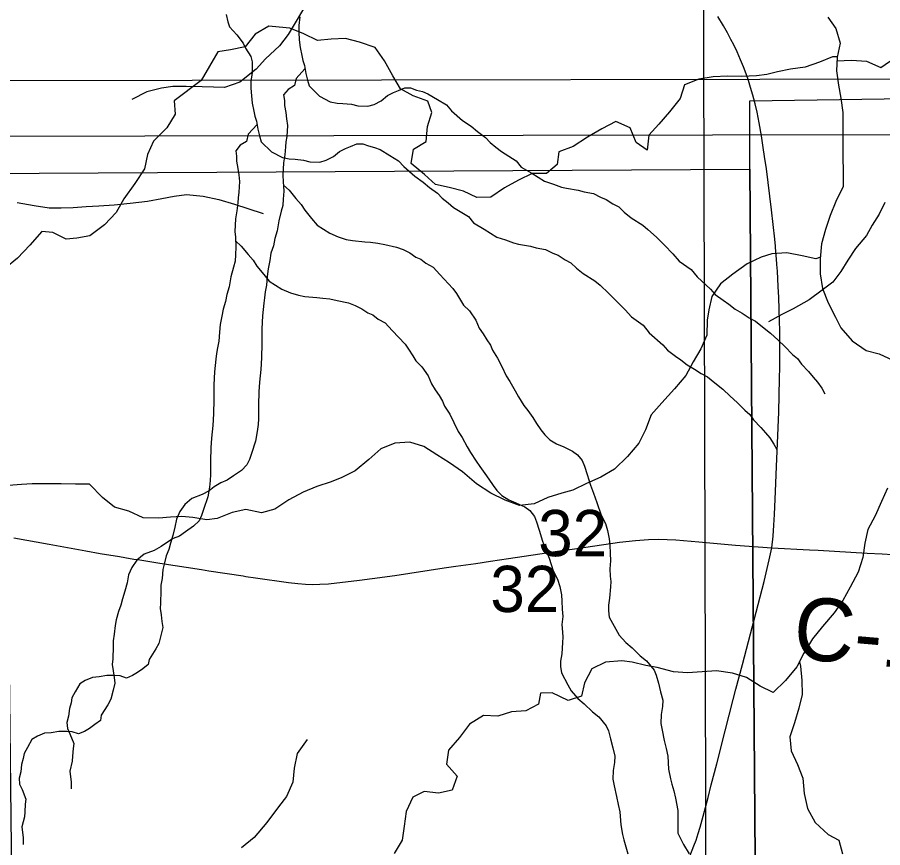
# Model space of a CAD drawing. Extents: x -21.1 to 50.3, y 0 to 22.1.
# Drawn here: x 3.837 to 4.62, y 19.324 to 20.075 of the extents above; entities that cross this region are included whole.
import ezdxf

# ---------------------------------------------------------------- set-up
doc = ezdxf.new("R2010")
doc.units = 0
for name, color, linetype in [('GM_X_County_Road', 7, 'Continuous'), ('GM_X_County_Road_Text', 7, 'Continuous'), ('GM_X_Minor_River', 7, 'Continuous'), ('GM_X_Section', 7, 'Continuous'), ('GM_X_Section_Text', 7, 'Continuous'), ('GM_X_State_Route', 7, 'Continuous'), ('GM_X_Township_Road', 7, 'Continuous')]:
    doc.layers.add(name, color=color, linetype=linetype)

msp = doc.modelspace()

# ---------------------------------------------------------------- linework, layer by layer
at = {"layer": 'GM_X_County_Road'}
msp.add_lwpolyline([(4.5196, 19.59528), (4.55358, 19.59321), (4.56138, 19.5929), (4.60576, 19.5903), (4.61927, 19.58967), (4.64742, 19.58801), (4.6643, 19.58714), (4.68714, 19.58536), (4.72573, 19.58133)], dxfattribs=at)
at = {"layer": 'GM_X_Minor_River'}
for points in [[(4.09721, 20.08514), (4.09, 20.07339), (4.08203, 20.05973), (4.07406, 20.04949), (4.06155, 20.03773), (4.0532, 20.02825), (4.03841, 20.01649), (4.02439, 20.01156), (4.01453, 20.01194), (4.00429, 20.01231), (3.98989, 20.01269), (3.97776, 20.01269), (3.96752, 20.01117), (3.95425, 20.00776), (3.9406, 20.00093)], [(4.02587, 20.07787), (4.02743, 20.07105), (4.02898, 20.0665), (4.03549, 20.05932), (4.04124, 20.05175), (4.04355, 20.0472), (4.04816, 20.03963), (4.04933, 20.03508), (4.04938, 20.0252), (4.04828, 20.01722), (4.04832, 20.01114), (4.04874, 20.0043), (4.04954, 19.99747), (4.0511, 19.99026), (4.05189, 19.98571), (4.05344, 19.98116), (4.05462, 19.97394), (4.05618, 19.96787), (4.05773, 19.96257), (4.06692, 19.9535), (4.07684, 19.94824), (4.08294, 19.94713), (4.08827, 19.94678), (4.09589, 19.94606), (4.1016, 19.94457), (4.11074, 19.94425), (4.11644, 19.9458), (4.12289, 19.94925), (4.12858, 19.95384), (4.13389, 19.95653), (4.13845, 19.95846), (4.14415, 19.96076)], [(4.57835, 20.03585), (4.57832, 20.03582), (4.5915, 20.03659), (4.6052, 20.03547), (4.61814, 20.02978), (4.63068, 20.03854), (4.64208, 20.05187), (4.65502, 20.05455), (4.66641, 20.06597), (4.67553, 20.07853)], [(4.09267, 20.07572), (4.09157, 20.06773), (4.09161, 20.06166), (4.09203, 20.05482), (4.09283, 20.04798), (4.09439, 20.04078), (4.09518, 20.03622), (4.09673, 20.03167), (4.09791, 20.02446), (4.09947, 20.01839), (4.10102, 20.01308), (4.1102, 20.00401), (4.12013, 19.99875), (4.12623, 19.99764), (4.13156, 19.9973), (4.13918, 19.99658), (4.14489, 19.99509), (4.15403, 19.99476), (4.15973, 19.99631), (4.16618, 19.99977), (4.17187, 20.00436), (4.17718, 20.00705), (4.18174, 20.00897), (4.18743, 20.01128)], [(4.57013, 20.07536), (4.57738, 20.0651), (4.5812, 20.05179), (4.57856, 20.03924), (4.57782, 20.02669), (4.57974, 20.01376), (4.58203, 20.00197), (4.58358, 19.98904), (4.58364, 19.94873), (4.58403, 19.9358), (4.58405, 19.92211), (4.57722, 19.90841), (4.57229, 19.89585), (4.56813, 19.88329), (4.56434, 19.87036), (4.56322, 19.85667), (4.56324, 19.84297), (4.56516, 19.82967), (4.57051, 19.81674), (4.577, 19.80382), (4.58196, 19.79432), (4.59225, 19.78254), (4.60482, 19.77381), (4.61662, 19.77078), (4.6288, 19.76509)], [(4.57863, 20.0396), (4.57449, 20.0396), (4.56258, 20.03465), (4.54965, 20.03007), (4.53634, 20.02816), (4.52455, 20.02586), (4.51504, 20.02357), (4.50552, 20.02241), (4.49221, 20.02164), (4.47927, 20.022), (4.46634, 20.02122), (4.4534, 20.01931), (4.44047, 20.01397), (4.43668, 20.00179), (4.42681, 19.98961), (4.41731, 19.97857), (4.40819, 19.96867), (4.40669, 19.95497), (4.39679, 19.96181), (4.39144, 19.97511), (4.3785, 19.9808), (4.36557, 19.97432), (4.35264, 19.9667), (4.33972, 19.95831), (4.32679, 19.95335), (4.32528, 19.94194), (4.31578, 19.93394), (4.30285, 19.93393), (4.2903, 19.92783), (4.27775, 19.92097), (4.26521, 19.91258), (4.25265, 19.91219), (4.24047, 19.91788), (4.22753, 19.92128), (4.21534, 19.92393), (4.20544, 19.93304), (4.19325, 19.94292), (4.19551, 19.95585), (4.20692, 19.96271), (4.20804, 19.97641), (4.21183, 19.98896), (4.20839, 19.99923), (4.19506, 20.00415), (4.18364, 20.0106), (4.17677, 20.02239), (4.16914, 20.03569), (4.16075, 20.04785), (4.14667, 20.05277), (4.13372, 20.05618), (4.12079, 20.0554), (4.10861, 20.05425), (4.09605, 20.06032), (4.08349, 20.06525), (4.07397, 20.06638), (4.06446, 20.06712), (4.05229, 20.05988), (4.04318, 20.04846), (4.02986, 20.04578), (4.01845, 20.04387), (4.01086, 20.03093), (4.00327, 20.01799), (3.97894, 19.9997), (3.97972, 19.98753), (3.97213, 19.97535), (3.96035, 19.96317), (3.95466, 19.95099), (3.95202, 19.93806), (3.94328, 19.92473), (3.93341, 19.91103), (3.92658, 19.89847), (3.91594, 19.88743), (3.90264, 19.87752), (3.89085, 19.87523), (3.88134, 19.87446), (3.86915, 19.88053), (3.85926, 19.88127), (3.84824, 19.86909), (3.83722, 19.85728), (3.82544, 19.84776)], [(4.09722, 20.02863), (4.08918, 20.01985), (4.08769, 20.01339), (4.082, 20.00994), (4.07784, 20.00497), (4.07863, 20.00004), (4.07866, 19.99548), (4.07984, 19.98903), (4.08063, 19.98334), (4.08142, 19.97726), (4.08072, 19.96738), (4.07999, 19.96244), (4.07963, 19.95788), (4.07891, 19.95066), (4.07781, 19.94343), (4.07711, 19.93203), (4.07752, 19.92671), (4.07795, 19.91798), (4.07761, 19.91076), (4.07726, 19.90506), (4.07577, 19.89973), (4.07353, 19.89098), (4.07206, 19.88186), (4.06982, 19.87501), (4.06871, 19.86854), (4.06647, 19.86169), (4.06536, 19.85523), (4.06388, 19.84762), (4.06316, 19.84078), (4.06244, 19.8328), (4.06133, 19.82671), (4.0606, 19.82139), (4.05987, 19.81645), (4.05879, 19.80504), (4.0581, 19.79326), (4.05817, 19.77997), (4.05786, 19.76705), (4.05716, 19.75641), (4.05608, 19.74501), (4.05537, 19.73627), (4.05506, 19.72449), (4.05513, 19.71195), (4.05477, 19.70663), (4.05405, 19.70055), (4.05257, 19.6918), (4.04883, 19.68039), (4.04696, 19.67506), (4.0447, 19.67011), (4.03978, 19.66514), (4.03258, 19.66016), (4.02689, 19.65633), (4.02119, 19.65402), (4.01512, 19.65019), (4.01058, 19.64674), (4.00412, 19.64329), (3.99501, 19.63982), (3.98857, 19.63446), (3.98403, 19.62798), (3.98103, 19.62113), (3.97954, 19.6139), (3.97768, 19.60629), (3.97544, 19.59944), (3.97395, 19.59373), (3.9717, 19.58802), (3.96984, 19.58041), (3.96872, 19.57547), (3.96801, 19.56749), (3.9669, 19.56141), (3.96693, 19.55647), (3.96661, 19.54507), (3.96626, 19.54013), (3.96705, 19.53444), (3.96785, 19.52836), (3.96864, 19.52305), (3.96715, 19.51696), (3.96491, 19.50859), (3.96227, 19.50364), (3.95624, 19.49411), (3.9555, 19.48955), (3.95058, 19.48572), (3.94565, 19.48227), (3.94109, 19.47959), (3.93578, 19.47728), (3.93006, 19.47915), (3.92511, 19.4795), (3.91787, 19.47946), (3.91103, 19.47828), (3.90494, 19.47787), (3.89848, 19.47517), (3.89355, 19.47211), (3.88941, 19.46486), (3.88639, 19.45953), (3.88565, 19.45497), (3.88416, 19.44964), (3.88344, 19.4428), (3.88195, 19.43709), (3.88236, 19.43177), (3.88467, 19.42685), (3.88815, 19.41813), (3.88741, 19.41357), (3.88707, 19.40673)], [(4.18743, 20.01128), (4.19276, 20.01131), (4.1981, 20.00944), (4.20344, 20.00795), (4.2084, 20.00608), (4.21718, 20.00081), (4.22521, 19.99592), (4.2298, 19.99063), (4.23975, 19.98194), (4.24739, 19.97667), (4.25313, 19.97176), (4.26039, 19.96648), (4.2646, 19.96195), (4.26996, 19.9578), (4.27493, 19.95365), (4.2883, 19.94536), (4.2929, 19.93969), (4.30244, 19.93404), (4.3139, 19.92689), (4.32191, 19.92428), (4.32916, 19.92166), (4.33373, 19.92054), (4.3444, 19.9187), (4.34974, 19.91721), (4.35812, 19.91574), (4.36461, 19.91236), (4.36957, 19.91048), (4.37568, 19.90634), (4.38103, 19.90371), (4.38601, 19.8988), (4.39212, 19.89389), (4.40282, 19.88712), (4.40741, 19.88334), (4.41506, 19.87617), (4.42233, 19.86899), (4.42999, 19.86105), (4.43574, 19.85463), (4.44644, 19.84709), (4.45181, 19.84028), (4.46405, 19.82933), (4.46826, 19.82442), (4.47553, 19.81914), (4.48049, 19.81575), (4.48623, 19.81122), (4.49272, 19.80746), (4.49883, 19.80331), (4.50456, 19.80031), (4.51106, 19.79502), (4.51833, 19.78937), (4.52521, 19.78295), (4.53133, 19.77728), (4.53823, 19.7701), (4.54282, 19.76633), (4.54627, 19.76141), (4.55278, 19.75461), (4.55699, 19.74969), (4.56083, 19.74516), (4.56466, 19.73948), (4.56736, 19.73455)], [(4.05393, 19.97811), (4.04589, 19.96934), (4.0444, 19.96287), (4.03871, 19.95942), (4.03455, 19.95446), (4.03534, 19.94952), (4.03537, 19.94497), (4.03655, 19.93851), (4.03734, 19.93282), (4.03813, 19.92675), (4.03743, 19.91686), (4.0367, 19.91192), (4.03634, 19.90736), (4.03562, 19.90014), (4.03452, 19.89292), (4.03382, 19.88151), (4.03423, 19.8762), (4.03466, 19.86746), (4.03432, 19.86024), (4.03397, 19.85454), (4.03248, 19.84922), (4.03024, 19.84047), (4.02877, 19.83134), (4.02653, 19.82449), (4.02542, 19.81803), (4.02318, 19.81118), (4.02207, 19.80471), (4.02059, 19.7971), (4.01987, 19.79026), (4.01915, 19.78228), (4.01804, 19.7762), (4.01731, 19.77087), (4.01658, 19.76593), (4.0155, 19.75453), (4.01481, 19.74275), (4.01488, 19.72945), (4.01457, 19.71653), (4.01387, 19.7059), (4.01279, 19.69449), (4.01208, 19.68575), (4.01177, 19.67397), (4.01184, 19.66144), (4.01149, 19.65611), (4.01076, 19.65003), (4.00928, 19.64129), (4.00554, 19.62987), (4.00367, 19.62454), (4.00141, 19.61959), (3.99649, 19.61462), (3.98929, 19.60965), (3.9836, 19.60581), (3.9779, 19.6035), (3.97183, 19.59967), (3.96729, 19.59623), (3.96083, 19.59277), (3.95172, 19.5893), (3.94528, 19.58395), (3.94074, 19.57747), (3.93774, 19.57061), (3.93626, 19.56338), (3.9344, 19.55578), (3.93215, 19.54893), (3.93066, 19.54322), (3.92841, 19.53751), (3.92655, 19.5299), (3.92543, 19.52496), (3.92472, 19.51697), (3.92361, 19.51089), (3.92364, 19.50595), (3.92332, 19.49455), (3.92297, 19.48961), (3.92376, 19.48392), (3.92456, 19.47785), (3.92535, 19.47253), (3.92386, 19.46644), (3.92162, 19.45807), (3.91899, 19.45312), (3.91295, 19.44359), (3.91221, 19.43903), (3.90729, 19.4352), (3.90236, 19.43175), (3.8978, 19.42907), (3.89249, 19.42676), (3.88677, 19.42863), (3.88182, 19.42898), (3.87458, 19.42894), (3.86774, 19.42776), (3.86165, 19.42735), (3.8552, 19.42465), (3.85026, 19.42159), (3.84612, 19.41435), (3.8431, 19.40901), (3.84237, 19.40445), (3.84087, 19.39912), (3.84015, 19.39228), (3.83866, 19.38657), (3.83907, 19.38126), (3.84138, 19.37633), (3.84486, 19.36762), (3.84412, 19.36305), (3.84378, 19.35621)], [(4.14415, 19.96076), (4.14948, 19.9608), (4.15481, 19.95893), (4.16015, 19.95743), (4.16511, 19.95556), (4.1739, 19.95029), (4.18192, 19.9454), (4.18652, 19.94011), (4.19646, 19.93143), (4.2041, 19.92615), (4.20984, 19.92124), (4.2171, 19.91597), (4.22131, 19.91143), (4.22667, 19.90728), (4.23164, 19.90313), (4.24501, 19.89485), (4.24961, 19.88917), (4.25916, 19.88353), (4.27062, 19.87637), (4.27862, 19.87376), (4.28587, 19.87114), (4.29044, 19.87003), (4.30111, 19.86818), (4.30645, 19.8667), (4.31483, 19.86522), (4.32132, 19.86184), (4.32628, 19.85997), (4.3324, 19.85582), (4.33774, 19.85319), (4.34272, 19.84828), (4.34884, 19.84338), (4.35953, 19.8366), (4.36412, 19.83283), (4.37177, 19.82565), (4.37905, 19.81847), (4.3867, 19.81054), (4.39245, 19.80411), (4.40315, 19.79657), (4.40852, 19.78977), (4.42076, 19.77882), (4.42497, 19.7739), (4.43224, 19.76862), (4.4372, 19.76523), (4.44294, 19.76071), (4.44943, 19.75694), (4.45554, 19.7528), (4.46127, 19.74979), (4.46777, 19.74451), (4.47504, 19.73885), (4.48192, 19.73243), (4.48805, 19.72677), (4.49494, 19.71959), (4.49953, 19.71581), (4.50298, 19.7109), (4.50949, 19.70409), (4.5137, 19.69918), (4.51754, 19.69464), (4.52138, 19.68896), (4.52407, 19.68404)], [(4.07769, 19.92332), (4.08289, 19.91877), (4.08903, 19.9112), (4.09362, 19.90591), (4.09708, 19.90061), (4.10321, 19.89305), (4.1082, 19.887), (4.11965, 19.87984), (4.12729, 19.87646), (4.13453, 19.87423), (4.14025, 19.87312), (4.15129, 19.87204), (4.15662, 19.87169), (4.1631, 19.87097), (4.16958, 19.86948), (4.17987, 19.86726), (4.18597, 19.86502), (4.19208, 19.86201), (4.19743, 19.85824), (4.20201, 19.85637), (4.2066, 19.85259), (4.21309, 19.84921), (4.21922, 19.84241), (4.23108, 19.82994), (4.23416, 19.8254), (4.238, 19.81934), (4.24069, 19.81479), (4.24604, 19.80951), (4.2518, 19.80118), (4.25489, 19.79398), (4.25834, 19.78868), (4.2618, 19.78338), (4.26487, 19.77846), (4.2668, 19.77391), (4.27141, 19.76672), (4.27526, 19.75914), (4.27911, 19.75081), (4.28257, 19.74551), (4.28718, 19.73718), (4.29026, 19.73187), (4.29525, 19.72392), (4.2987, 19.71938), (4.3033, 19.71295), (4.30676, 19.70765), (4.3106, 19.70198), (4.31405, 19.69744), (4.31864, 19.69291), (4.32476, 19.68914), (4.33124, 19.68652), (4.33926, 19.68276), (4.34384, 19.67937), (4.34806, 19.67407), (4.34999, 19.66915), (4.35232, 19.66156), (4.35542, 19.6517), (4.35812, 19.6445), (4.36122, 19.63616), (4.36508, 19.62478), (4.36893, 19.61721), (4.37087, 19.61076), (4.37244, 19.60317), (4.37285, 19.59748), (4.37327, 19.59026), (4.37369, 19.58342), (4.37297, 19.5762), (4.37339, 19.56937), (4.37379, 19.56481), (4.37344, 19.55987), (4.37274, 19.54961), (4.37163, 19.54314), (4.37166, 19.53821), (4.37245, 19.53251), (4.37823, 19.52153), (4.3813, 19.51623), (4.38743, 19.50942), (4.39317, 19.50452), (4.40044, 19.49734), (4.40617, 19.49281), (4.41307, 19.48449), (4.415, 19.47995), (4.41694, 19.47274), (4.41889, 19.46477), (4.42084, 19.45718), (4.42049, 19.45148), (4.41939, 19.44426), (4.41905, 19.43628), (4.42023, 19.43021), (4.42218, 19.42072), (4.42375, 19.41352), (4.42531, 19.40669), (4.42614, 19.39491), (4.42771, 19.38619), (4.42888, 19.38125), (4.43082, 19.37519), (4.43237, 19.36874), (4.43434, 19.35735), (4.43446, 19.33684), (4.43946, 19.32661), (4.44484, 19.31828)], [(3.83702, 19.90757), (3.85217, 19.90506), (3.86581, 19.90295), (3.87682, 19.90279), (3.88746, 19.903), (3.89925, 19.90397), (3.91066, 19.90455), (3.92472, 19.90548), (3.93918, 19.90716), (3.95478, 19.90882), (3.96774, 19.91129), (3.97878, 19.9134), (3.9902, 19.91474), (4.00499, 19.91338), (4.01938, 19.9105), (4.03336, 19.90611), (4.04546, 19.90213), (4.05944, 19.89774)], [(4.62175, 19.9077), (4.61644, 19.89708), (4.61037, 19.88722), (4.60506, 19.87774), (4.5952, 19.86598), (4.58836, 19.85536), (4.58192, 19.84512), (4.57471, 19.83564), (4.56485, 19.82843), (4.55309, 19.8197), (4.53868, 19.81136), (4.52844, 19.80643), (4.51631, 19.7996)], [(4.0344, 19.8728), (4.0396, 19.86825), (4.04574, 19.86069), (4.05034, 19.85539), (4.05379, 19.85009), (4.05992, 19.84253), (4.06491, 19.83648), (4.07637, 19.82932), (4.084, 19.82595), (4.09124, 19.82371), (4.09696, 19.8226), (4.108, 19.82152), (4.11334, 19.82117), (4.11981, 19.82045), (4.12629, 19.81897), (4.13658, 19.81675), (4.14268, 19.8145), (4.14879, 19.81149), (4.15414, 19.80773), (4.15872, 19.80585), (4.16331, 19.80208), (4.1698, 19.79869), (4.17593, 19.79189), (4.1878, 19.77942), (4.19087, 19.77488), (4.19471, 19.76882), (4.1974, 19.76428), (4.20276, 19.75899), (4.20851, 19.75066), (4.2116, 19.74347), (4.21506, 19.73816), (4.21851, 19.73286), (4.22158, 19.72794), (4.22351, 19.7234), (4.22812, 19.7162), (4.23197, 19.70863), (4.23582, 19.70029), (4.23928, 19.69499), (4.24389, 19.68666), (4.24697, 19.68136), (4.25196, 19.67341), (4.25541, 19.66887), (4.26002, 19.66244), (4.26347, 19.65714), (4.26731, 19.65146), (4.27076, 19.64692), (4.27535, 19.64239), (4.28147, 19.63862), (4.28795, 19.636), (4.29597, 19.63225), (4.30055, 19.62885), (4.30477, 19.62356), (4.3067, 19.61863), (4.30903, 19.61104), (4.31213, 19.60118), (4.31483, 19.59398), (4.31793, 19.58564), (4.32179, 19.57427), (4.32564, 19.56669), (4.32758, 19.56024), (4.32915, 19.55265), (4.32956, 19.54696), (4.32998, 19.53974), (4.3304, 19.53291), (4.32968, 19.52568), (4.3301, 19.51885), (4.33051, 19.51429), (4.33015, 19.50935), (4.32945, 19.49909), (4.32835, 19.49263), (4.32837, 19.48769), (4.32917, 19.482), (4.33494, 19.47101), (4.33801, 19.46571), (4.34414, 19.45891), (4.34988, 19.454), (4.35715, 19.44682), (4.36288, 19.4423), (4.36978, 19.43398), (4.37171, 19.42943), (4.37366, 19.42222), (4.3756, 19.41425), (4.37755, 19.40667), (4.3772, 19.40097), (4.3761, 19.39374), (4.37576, 19.38576), (4.37694, 19.37969), (4.3789, 19.37021), (4.38046, 19.363), (4.38202, 19.35617), (4.38285, 19.3444), (4.38442, 19.33567), (4.38559, 19.33074), (4.38753, 19.32467), (4.38909, 19.31822)], [(4.56335, 19.85821), (4.55942, 19.85666), (4.54685, 19.85931), (4.53315, 19.86195), (4.51946, 19.86117), (4.50995, 19.85812), (4.49702, 19.85202), (4.4841, 19.84288), (4.47307, 19.83411), (4.4651, 19.8227), (4.46246, 19.81052), (4.46095, 19.80101), (4.46059, 19.7877), (4.45528, 19.77514), (4.44844, 19.76335), (4.44161, 19.75117), (4.43136, 19.73898), (4.41996, 19.72642), (4.41046, 19.71538), (4.40516, 19.70206), (4.39909, 19.68988), (4.38883, 19.6777), (4.37705, 19.66628), (4.36489, 19.65903), (4.35196, 19.65332), (4.33941, 19.64721), (4.32952, 19.64454), (4.31697, 19.64072), (4.30442, 19.635), (4.29111, 19.63346), (4.27816, 19.63839), (4.26522, 19.64446), (4.25227, 19.65319), (4.2397, 19.66382), (4.22789, 19.67217), (4.21646, 19.67939), (4.20466, 19.68698), (4.19209, 19.69077), (4.17839, 19.68999), (4.16585, 19.68465), (4.15483, 19.67513), (4.14267, 19.66484), (4.1305, 19.65874), (4.12099, 19.65493), (4.10806, 19.65073), (4.09551, 19.64539), (4.08259, 19.63853), (4.07004, 19.63014), (4.05787, 19.62671), (4.04379, 19.62973), (4.03123, 19.62705), (4.01792, 19.62171), (4.00841, 19.62056), (3.99585, 19.62245), (3.98596, 19.62357), (3.97569, 19.6228), (3.96503, 19.62203), (3.95096, 19.62239), (3.93801, 19.62846), (3.92507, 19.63187), (3.91402, 19.6406), (3.90221, 19.65275), (3.88965, 19.65274), (3.87671, 19.6531), (3.85046, 19.65307), (3.84095, 19.6523), (3.82915, 19.65152)], [(4.62402, 19.64909), (4.61871, 19.63691), (4.61302, 19.62397), (4.60619, 19.61179), (4.60355, 19.59924), (4.60166, 19.58631), (4.5975, 19.57299), (4.59029, 19.55967), (4.58384, 19.54749), (4.57586, 19.53646), (4.56523, 19.52389), (4.55611, 19.51285), (4.54852, 19.49991), (4.54207, 19.48735), (4.53181, 19.47517), (4.52079, 19.46413), (4.50899, 19.46982), (4.49642, 19.47779), (4.48386, 19.48157), (4.4694, 19.48384), (4.45646, 19.48306), (4.44315, 19.4819), (4.43059, 19.48303), (4.41574, 19.48682), (4.40547, 19.4887), (4.39329, 19.49173), (4.38377, 19.49286), (4.36893, 19.4917), (4.35677, 19.4856), (4.34994, 19.47304), (4.34729, 19.46087), (4.33512, 19.45705), (4.32065, 19.46388), (4.31038, 19.46348), (4.30849, 19.45359), (4.29708, 19.44749), (4.28415, 19.44672), (4.2716, 19.4429), (4.25866, 19.44326), (4.24611, 19.43564), (4.237, 19.42346), (4.22712, 19.41204), (4.22524, 19.39948), (4.23477, 19.38847), (4.23022, 19.37591), (4.21805, 19.37323), (4.20511, 19.37474), (4.19484, 19.3694), (4.18878, 19.35646), (4.18689, 19.34315), (4.18501, 19.3306), (4.17779, 19.31842)], [(4.5444, 19.4919), (4.54549, 19.48812), (4.54665, 19.47519), (4.54705, 19.46226), (4.54403, 19.45008), (4.53986, 19.43677), (4.53569, 19.42421), (4.53685, 19.41128), (4.54258, 19.39912), (4.54754, 19.38657), (4.54871, 19.37289), (4.55177, 19.3592), (4.55864, 19.34665), (4.57045, 19.33564), (4.57996, 19.33071), (4.58341, 19.31816)], [(4.09912, 19.42181), (4.09002, 19.40891), (4.08736, 19.39564), (4.08622, 19.38312), (4.08052, 19.37022), (4.07332, 19.36074), (4.06269, 19.34671), (4.05132, 19.33305), (4.03994, 19.32357)], [(3.88707, 19.40673), (3.88671, 19.40217), (3.88448, 19.39304), (3.88568, 19.38317), (3.88571, 19.37709)], [(3.84378, 19.35621), (3.84342, 19.35165), (3.84119, 19.34252), (3.84239, 19.33265), (3.84242, 19.32658)]]:
    msp.add_lwpolyline(points, dxfattribs=at)
at = {"layer": 'GM_X_Section'}
for points in [[(4.45774, 20.15268), (5.46449, 20.1514), (5.46172, 19.1492), (4.46024, 19.14326)], [(3.82397, 20.01814), (4.85115, 20.01985), (4.855, 19.00483), (4.83075, 19.0046), (3.83539, 19.00471)], [(4.49952, 19.99963), (5.45185, 20.01395), (5.47114, 18.99721), (4.50668, 19.00183), (4.49957, 19.93786)], [(3.78068, 19.96762), (4.80786, 19.96933), (4.81171, 18.95431), (4.78746, 18.95409), (3.7921, 18.95419)], [(3.4813, 19.9322), (4.49957, 19.93786), (4.50668, 19.00183), (4.50596, 18.94006), (3.48506, 18.92038)]]:
    msp.add_lwpolyline(points, close=True, dxfattribs=at)
at = {"layer": 'GM_X_State_Route'}
for points in [[(4.5196, 19.59528), (4.52062, 19.60572), (4.52135, 19.61563), (4.52181, 19.62522), (4.52273, 19.64598), (4.52375, 19.66877), (4.52569, 19.71785), (4.52642, 19.7483), (4.5267, 19.75873), (4.52679, 19.78022), (4.52669, 19.79157), (4.52651, 19.80043), (4.52569, 19.82174), (4.52513, 19.83171), (4.52449, 19.84545), (4.52412, 19.85145), (4.52375, 19.85653), (4.52322, 19.86252), (4.52273, 19.86806), (4.52207, 19.87445), (4.51932, 19.90099), (4.51452, 19.93808), (4.51296, 19.94934), (4.51176, 19.95755), (4.51018, 19.96797), (4.50815, 19.97979), (4.50622, 19.98938), (4.50447, 19.99686), (4.50322, 20.00148), (4.50234, 20.0047), (4.50031, 20.01171), (4.49828, 20.01816), (4.49635, 20.02407), (4.49376, 20.03053), (4.49118, 20.03671), (4.48804, 20.044), (4.48509, 20.05018), (4.48251, 20.05507), (4.47928, 20.06107), (4.4757, 20.06743), (4.4707, 20.07583)], [(4.44518, 19.31623), (4.44903, 19.32548), (4.451, 19.33067), (4.45297, 19.3367), (4.45475, 19.34242), (4.45568, 19.34564), (4.45734, 19.35218), (4.46192, 19.36913), (4.46472, 19.38067), (4.46961, 19.39979), (4.4772, 19.42951), (4.48447, 19.45778), (4.48686, 19.46714), (4.49288, 19.48959), (4.51243, 19.56473), (4.51716, 19.58442), (4.5196, 19.59528)]]:
    msp.add_lwpolyline(points, dxfattribs=at)
at = {"layer": 'GM_X_Township_Road'}
msp.add_lwpolyline([(3.83395, 19.60422), (3.86574, 19.59843), (3.89886, 19.59246), (3.91207, 19.59008), (3.92936, 19.58718), (3.93425, 19.58645), (3.94256, 19.585), (3.94797, 19.58417), (3.96603, 19.58128), (4.00374, 19.57547), (4.01038, 19.57444), (4.04125, 19.56968), (4.04378, 19.56929), (4.05251, 19.56794), (4.08225, 19.56369), (4.09067, 19.56275), (4.09783, 19.56223), (4.10408, 19.56203), (4.11071, 19.56226), (4.11852, 19.56265), (4.14658, 19.56577), (4.15791, 19.56733), (4.1786, 19.57024), (4.22318, 19.5771), (4.23378, 19.57855), (4.25187, 19.58105), (4.26507, 19.58302), (4.28118, 19.58551), (4.30955, 19.58967), (4.32338, 19.59175), (4.34322, 19.59466), (4.38178, 19.60017), (4.39613, 19.60183), (4.40795, 19.60273), (4.41691, 19.60298), (4.42491, 19.60277), (4.4325, 19.60225), (4.4535, 19.60048), (4.48675, 19.59768), (4.5196, 19.59528)], dxfattribs=at)

# ---------------------------------------------------------------- texts
at = {"layer": 'GM_X_County_Road_Text'}
msp.add_text('C-140', height=0.056818, rotation=355.1012, dxfattribs=at).set_placement((4.53746, 19.49509))
at = {"layer": 'GM_X_Section_Text'}
for p in [(4.30818, 19.58755), (4.26489, 19.53703)]:
    msp.add_text('32', height=0.041856, rotation=0.00001, dxfattribs=at).set_placement(p)

doc.saveas('drawing.dxf')
